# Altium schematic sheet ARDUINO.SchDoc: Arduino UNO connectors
size A4; Author: N.P; CompanyName: STMicroelectronics; Organization: MCD/APPLIS/LMS; DocumentNumber: MB1260; SheetNumber: 12; SheetTotal: 13; Project: STM32F723e-DISCO
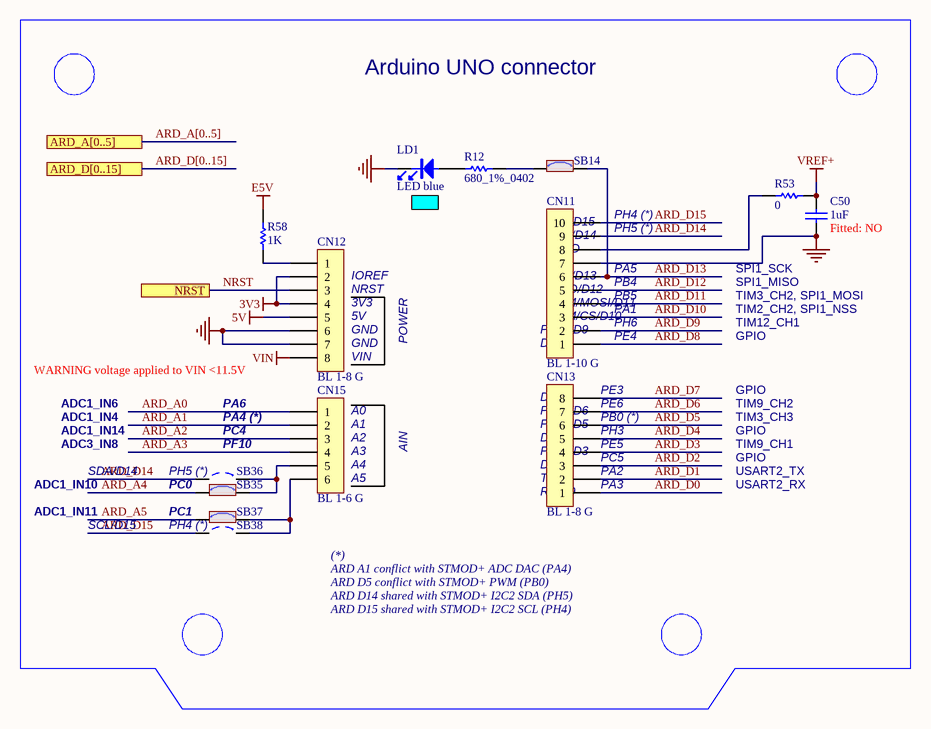
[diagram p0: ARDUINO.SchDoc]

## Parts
C50  1uF  Fitted: NO  [0603C]
CN11  BL 1-10 G  [HDR_1X10_2R54_W]
CN12  BL 1-8 G  [HDR_1X8_2R54_W]
CN13  BL 1-8 G  [HDR_1X8_2R54_W]
CN15  BL 1-6 G  [HDR_1X6_2R54_W]
LD1  LED blue  [0603D]
R12  680_1%_0402  [0402R]
R53  0  [0402R]
R58  1K  [0402R]
SB14  Solder Bridge ON  [JP2_SMD]  (value not drawn)
SB35  Solder Bridge ON  [JP2_SMD]  (value not drawn)
SB36  Solder Bridge OFF  [JP2_SMD]  (value not drawn)
SB37  Solder Bridge ON  [JP2_SMD]  (value not drawn)
SB38  Solder Bridge OFF  [JP2_SMD]  (value not drawn)

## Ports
ARD_A[0..5], ARD_D[0..15], NRST

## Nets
3V3: CN12.2 CN12.4
5V: CN12.5
E5V: R58.2
GND: C50.1 CN11.7 CN12.6 CN12.7 LD1.2
VIN: CN12.8
VREF+: C50.2 R53.2
ARD_A0: CN15.1
ARD_A1: CN15.2
ARD_A2: CN15.3
ARD_A3: CN15.4
ARD_A4: SB35.1
ARD_A5: SB37.1
ARD_D0: CN13.1
ARD_D1: CN13.2
ARD_D2: CN13.3
ARD_D3: CN13.4
ARD_D4: CN13.5
ARD_D5: CN13.6
ARD_D6: CN13.7
ARD_D7: CN13.8
ARD_D8: CN11.1
ARD_D9: CN11.2
ARD_D10: CN11.3
ARD_D11: CN11.4
ARD_D12: CN11.5
ARD_D13: CN11.6 SB14.2
ARD_D14: CN11.9 SB36.1
ARD_D15: CN11.10 SB38.1
NRST: CN12.3 ; port NRST
NetCN11_8: CN11.8 R53.1
NetCN12_1: CN12.1 R58.1
NetCN15_5: CN15.5 SB35.2 SB36.2
NetCN15_6: CN15.6 SB37.2 SB38.2
NetLD1_1: LD1.1 R12.1
NetR12_2: R12.2 SB14.1

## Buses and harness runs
bus ARD_A[0..5] = port ARD_A[0..5]
bus ARD_D[0..15] = port ARD_D[0..15]

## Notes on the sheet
- Arduino UNO connector
- PH4 (*)
- (near CN12) IOREF
- (near CN12) NRST
- (near CN11) SDA/D14
- (near CN11) SCL/D15
- (near CN11) SCK/D13
- (near CN11) MISO/D12
- (near CN11) AVDD
- (near CN11) GND
- (near CN11) PB4
- (near CN11) PA5
- (near CN11) PH5 (*)
- SPI1_MISO
- SPI1_SCK
- (near CN12) 3V3
- (near CN12) 5V
- (near CN12) GND
- POWER
- (near CN11) D8
- (near CN11) PWM/D9
- (near CN11) PWM/CS/D10
- (near CN11) PWM/MOSI/D11
- (near CN11) PA1
- (near CN11) PE4
- (near CN11) PH6
- (near CN11) PB5
- TIM12_CH1
- TIM2_CH2, SPI1_NSS
- TIM3_CH2, SPI1_MOSI
- GPIO
- WARNING voltage applied to VIN <11.5V
- ADC1_IN4
- ADC1_IN6
- PA6
- PA4 (*)
- (near CN15) A0
- (near CN15) A1
- (near CN12) VIN
- (near CN13) PWM/D5
- (near CN13) PWM/D6
- (near CN13) D7
- (near CN13) PE6
- (near CN13) PE3
- (near CN13) PB0 (*)
- TIM3_CH3
- TIM9_CH2
- ADC1_IN10
- ADC3_IN8
- ADC1_IN14
- SDA/D14
- (near SB36) PH5 (*)
- PC0
- PC4
- PF10
- (near CN15) A2
- (near CN15) A3
- (near CN15) A4
- (near CN15) A5
- AIN
- (near CN13) TX/D1
- (near CN13) D2
- (near CN13) D4
- (near CN13) PWM/D3
- (near CN13) PA2
- (near CN13) PC5
- (near CN13) PE5
- (near CN13) PH3
- (near CN13) PA3
- USART2_RX
- USART2_TX
- TIM9_CH1
- ADC1_IN11
- SCL/D15
- PC1
- (near CN13) RX/D0
- (*)
  ARD A1 conflict with STMOD+ ADC DAC (PA4)
  ARD D5 conflict with STMOD+ PWM (PB0)
  ARD D14 shared with STMOD+ I2C2 SDA (PH5)
  ARD D15 shared with STMOD+ I2C2 SCL (PH4)

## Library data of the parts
C50 = Cap_1uF_X5R_10%_0603: Capacitor,1uF,16V,X5R,10%,0603,YAGEO; Manuf_Part_1: CC0603KRX5R7BB105; Ordered by: Subcon
CN11 = Header 10X1_Female_THT: Header, 10-Pin, Single row, female, THT, 2.54; Manuf_1: Fischer Electronik; Ordered by: Subcon; Fitted: YES
CN12 CN13 = Header 8X1_Female_THT: Header, 8-Pins, Single row, female, THT, 2.54; Manuf_1: Fischer Electronik; Ordered by: Subcon; Fitted: YES
CN15 = Header 6X1_Female_THT: Header, 6-Pins, Single row, female THT, 2.54; Manuf_1: Fischer Electronik; Ordered by: Subcon; Fitted: YES
LD1 = LED_blue: LED blue 0603; Manuf_1: everlight; Manuf_Part_1: 19-213SUBC/S400-A5/S208-2/S4/TR8; ECCN_US/EU: EAR99/NEC; Fitted: YES; Ordered by: Subcon
R12 = Res_680_1%_0402: Resistor,680,0402,1%,YAGEO; Manuf_Part_1: RC0402FR-07680RL; Manuf_Part_2: RT0402FRE07680RL; Ordered by: Subcon; Fitted: YES; Value: 680
R53 = Res_0_5%_0402: Resistor,0,0402,5%,YAGEO; Manuf_Part_1: RC0402JR-070RL; Order: 2363467; Ordered by: Subcon; Fitted: YES
R58 = Res_1K_1%_0402: Resistor,1K,0402,1%,YAGEO; Manuf_Part_1: RC0402FR-071KL; Ordered by: Subcon; Fitted: YES
SB14 SB35 SB37 = SB_ON: Fitted: YES; Ordered by: Subcon
SB36 SB38 = SB_OFF: Fitted: NO; Ordered by: Subcon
